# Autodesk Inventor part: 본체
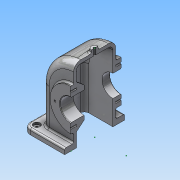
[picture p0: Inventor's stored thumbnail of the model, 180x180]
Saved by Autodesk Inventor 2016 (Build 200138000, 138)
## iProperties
Created: 2018-08
Part Number: 본체
Material: 알루미늄 6061
Document SubType Name: Modeling
Designer: Administrator
Density: 2.7 g/cm^3
Appearance: 알루미늄 - 평지
Mass: 1091.75 g
Surface Area: 1182.54 cm^2
Volume: 404.353 cm^3
Author: Administrator
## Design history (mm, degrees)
sketch "스케치1"
  geometry: L1 (-75, -55)-(75, -55); L2 (75, -55)-(75, 55); L3 (75, 55)-(-75, 55); L4 (-75, 55)-(-75, -55); L5 (-75, -55)-(75, 55); L6 (75, -55)-(-75, 55); 1 further point
  constraints: 12 end point, 2 midpoint, 2 parallel, 1 horizontal, 1 perpendicular
  dimensions: "d2" = 150 distance of L2.end L3.end; "d3" = 110 distance of L1.end L2.end
extrude "돌출1" new body sketch "스케치1" distance "d4" = 10; taper "d5" = 0 deg
sketch "스케치3"
  geometry: L1 (58, 10)-(-58, 10); L2 (-58, 10)-(-58, 78); L3 (58, 10)-(58, 78); L4 (0, 0)-(0, 18.41); L5 (75, 10)-(-75, 10) reference; L6 (-75, 0)-(75, 0) reference; A1 r 58 centre (0, 78) between (58, 78) and (-58, 78)
  constraints: 8 end point, 2 point on circle, 2 vertical, 1 centre point, 1 collinear, 1 horizontal, 1 perpendicular, 1 other
  dimensions: "d9" = 116 distance between parallel lines of L2 L3; "d10" = 58 radius of A1; "d11" = 78 distance from line of L6 A1.centre
extrude "돌출2" join sketch "스케치3" stored distance "d12" = 77; taper "d13" = 0 deg
sketch "스케치5"
  geometry: L1 (52, 0)-(-52, 0); L2 (-52, 0)-(-52, 78); L3 (52, 0)-(52, 78); L4 (0, 0)-(0, 10.195); L5 (-75, 0)-(75, 0) reference; A1 r 52 centre (0, 78) between (52, 78) and (-52, 78)
  constraints: 8 end point, 2 point on circle, 2 vertical, 1 centre point, 1 collinear, 1 horizontal, 1 perpendicular, 1 point on line, 1 other
  dimensions: "d27" = 52 radius of A1; "d28" = 78 distance from line of L1 A1.centre; "d29" = 104 distance between parallel lines of L2 L3
extrude "돌출3" cut sketch "스케치5" stored distance "d30" = 67; taper "d31" = 0 deg
sketch "스케치8"
  geometry: L1 (-60.344, 65)-(75.352, 65); L2 (33.5, 0)-(-33.5, 0) reference; L3 (-43.5, 65)-(-19.5, 65); L4 (-19.5, 65)-(-19.5, 93); L5 (-19.5, 93)-(-31.418, 103); L6 (-31.418, 103)-(-43.5, 103); L7 (-43.5, 103)-(-43.5, 65); L8 (-38.5, 136)-(-38.5, 78) reference; 1 further point
  constraints: 12 end point, 2 perpendicular, 2 point on line, 1 horizontal, 1 vertical
  dimensions: "d38" = 65 distance between parallel lines of L2 L1; "d39" = 50 deg angle of L4 L5; "d40" = 24 distance between parallel lines of L4 L7; "d41" = 5 distance between parallel lines of L8 L7; "d42" = 76 diameter of L6 L1; "d43" = 56 diameter of L4.end L1
revolve "회전1" sketch "스케치8" stored, may be unused: angle "d44" = 90 deg
sketch "스케치9"
  geometry: L1 (75, 0)-(-75, 0) reference; C1 r 38 at (0, -65); 2 further points
  constraints: 1 centre point, 1 midpoint, 1 vertical alignment
  dimensions: "d45" = 65 distance from line of L1 C1.centre; "d46" = 76 diameter of C1
extrude "돌출4" join sketch "스케치9" distance "d47" = 10; taper "d48" = 0 deg
node "작업 평면1"
sketch "스케치10"
  geometry: C1 r 6 at (0, 0); 1 further point
  constraints: 1 centre point, 1 coincident
  dimensions: "d50" = 12 diameter of C1
extrude "돌출5" join sketch "스케치10" stored distance "d51" = 10; taper "d52" = 5 deg
sketch "스케치11"
  geometry: 1 further point
hole "구멍1" diameter "d55" = 40; stored, may be unused: countersink angle "d59" = 90 deg, drill point angle "d61" = 118 deg; dims "d53" = 10, "d54" = 10, "d56" = 6, "d57" = 4, "d58" = 2, "d60" = 8
sketch "스케치12"
  geometry: C1 r 2 at (0, 29); C2 r 38 at (0, 0) reference; 1 further point
  constraints: 1 centre point, 1 vertical alignment
  dimensions: "d62" = 29 distance of C2.centre C1.centre; "d63" = 4 diameter of C1
hole "구멍2" sketch "스케치12" at (0, 29) diameter "d64" = 3.242; stored, may be unused: countersink angle "d68" = 90 deg, drill point angle "d70" = 118 deg; dims "d65" = 8, "d66" = 4, "d67" = 2, "d69" = 10
sketch "스케치13"
  geometry: C1 r 2 at (0, -29); C2 r 38 at (0, 0) reference; 1 further point
  constraints: 1 centre point, 1 vertical alignment
  dimensions: "d74" = 29 distance of C2.centre C1.centre; "d75" = 4 diameter of C1
hole "구멍3" sketch "스케치13" at (0, -29) diameter "d76" = 3.242; stored, may be unused: countersink angle "d80" = 90 deg, drill point angle "d82" = 118 deg; dims "d77" = 8, "d78" = 4, "d79" = 2, "d81" = 10
sketch "스케치14"
  geometry: 1 further point
hole "구멍4" diameter "d88" = 4.459; stored, may be unused: countersink angle "d92" = 90 deg, drill point angle "d94" = 118 deg; dims "d86" = 10, "d87" = 10, "d89" = 10, "d90" = 4, "d91" = 2, "d93" = 10
fillet "모깎기1" dims "d95" = 13
fillet "모깎기2" dims "d96" = 8
fillet "모깎기3" dims "d97" = 12
fillet "모깎기4" dims "d98" = 3
chamfer "모따기1" distance "d99" = 1; stored, may be unused: second distance "d100" = 2, angle "d101" = 45 deg
fillet "모깎기5" dims "d102" = 3
fillet "모깎기6" dims "d103" = 3
sketch "스케치15"
  geometry: 1 further point
sketch "스케치16"
  geometry: L1 (78, -17.5)-(78, 68.5) reference; L2 (0, -13)-(65, -13) reference; 2 further points
  constraints: 1 other
  dimensions: "d104" = 40 distance from line of L1 point (38, 25.5); "d105" = 38.5 distance from line of L2 point (38, 25.5)
feature "엠보싱1" sketch "스케치16" dims "d106" = 0.5, "d107" = 0
hole "구멍5" diameter "d110" = 5; stored, may be unused: countersink angle "d114" = 90 deg, drill point angle "d116" = 118 deg; dims "d108" = 10, "d109" = 10, "d111" = 10, "d112" = 12, "d113" = 4, "d115" = 12.8
hole "구멍6" diameter "d119" = 5; stored, may be unused: countersink angle "d123" = 90 deg, drill point angle "d125" = 118 deg; dims "d117" = 10, "d118" = 10, "d120" = 10, "d121" = 12, "d122" = 4, "d124" = 12.8
hole "구멍7" diameter "d128" = 5; stored, may be unused: countersink angle "d132" = 90 deg, drill point angle "d134" = 118 deg; dims "d126" = 10, "d127" = 10, "d129" = 10, "d130" = 12, "d131" = 4, "d133" = 12.8
hole "구멍8" diameter "d137" = 5; stored, may be unused: countersink angle "d141" = 90 deg, drill point angle "d143" = 118 deg; dims "d135" = 10, "d136" = 10, "d138" = 10, "d139" = 12, "d140" = 4, "d142" = 12.8
sketch "스케치17"
  geometry: 1 further point
sketch "스케치18"
  geometry: L1 (-81.637, 160.796)-(78.884, 160.796); L2 (78.884, 160.796)-(78.884, -25.331); L3 (78.884, -25.331)-(-81.637, -25.331); L4 (-81.637, -25.331)-(-81.637, 160.796); 1 further point
  constraints: 8 end point, 2 parallel, 1 horizontal, 1 perpendicular
extrude "돌출6" cut sketch "스케치18" stored distance "d144" = 10; taper "d145" = 0 deg
node "솔리드1"
pattern_circular "원형 패턴1" dims angle "d72" = 360 deg
pattern_circular "원형 패턴2" dims angle "d84" = 360 deg
other parameters: "d49" = 142
